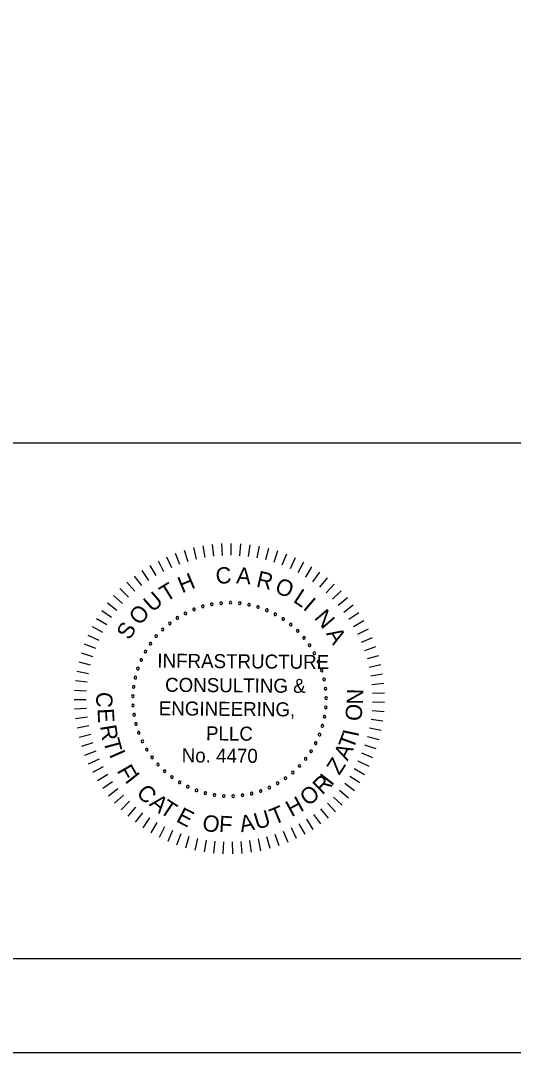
# Model space of a CAD drawing. Extents: x -125.5 to -89.4, y -5.1 to 16.9.
# Drawn here: x -100.31 to -97.69, y -5.07 to 0.43 of the extents above; entities that cross this region are included whole.
import ezdxf

# ---------------------------------------------------------------- set-up
doc = ezdxf.new("R2010")
doc.units = 0
for name, color, linetype in [('BR_BORDER LINES', 7, 'Continuous'), ('BR_TEXT', 7, 'Continuous'), ('Level 31', 7, 'Continuous')]:
    doc.layers.add(name, color=color, linetype=linetype)

msp = doc.modelspace()

# ---------------------------------------------------------------- linework, layer by layer
at = {"layer": 'BR_BORDER LINES'}
for p, q in [((-102.8989, -1.8161), (-97.5337, -1.8161)), ((-123.6994, -4.5662), (-90.0334, -4.5662))]:
    msp.add_line(p, q, dxfattribs=at)
at = {"layer": 'BR_TEXT'}
for p, q in [((-99.2931, -2.3579), (-99.2858, -2.4212)), ((-99.2427, -2.3538), (-99.2394, -2.4174)), ((-99.1923, -2.3527), (-99.1928, -2.4164)), ((-99.1418, -2.3548), (-99.1462, -2.4183)), ((-99.0916, -2.3599), (-99.0999, -2.423)), ((-99.489, -2.4048), (-99.4667, -2.4644)), ((-99.4412, -2.3886), (-99.4226, -2.4495)), ((-99.3925, -2.3754), (-99.3776, -2.4373)), ((-99.343, -2.3651), (-99.332, -2.4278)), ((-99.0418, -2.368), (-99.0539, -2.4305)), ((-98.9925, -2.3792), (-99.0084, -2.4408)), ((-98.9441, -2.3933), (-98.9637, -2.4539)), ((-98.8966, -2.4104), (-98.9199, -2.4696)), ((-99.6253, -2.4703), (-99.5926, -2.5249)), ((-99.5813, -2.4457), (-99.5519, -2.5022)), ((-99.5358, -2.4238), (-99.5099, -2.482)), ((-98.8502, -2.4303), (-98.877, -2.488)), ((-98.8051, -2.453), (-98.8354, -2.509)), ((-99.7086, -2.5273), (-99.6694, -2.5775)), ((-99.6678, -2.4975), (-99.6318, -2.55)), ((-98.7615, -2.4785), (-98.7952, -2.5325)), ((-98.7195, -2.5065), (-98.7564, -2.5584)), ((-99.7475, -2.5595), (-99.7053, -2.6072)), ((-98.6793, -2.5371), (-98.7193, -2.5866)), ((-98.6411, -2.57), (-98.684, -2.617)), ((-99.819, -2.6308), (-99.7713, -2.673)), ((-99.7843, -2.5941), (-99.7393, -2.6391)), ((-98.6049, -2.6052), (-98.6506, -2.6495)), ((-99.8513, -2.6695), (-99.8012, -2.7087)), ((-98.571, -2.6426), (-98.6193, -2.684)), ((-98.5393, -2.6819), (-98.5901, -2.7204)), ((-99.8813, -2.7102), (-99.8288, -2.7463)), ((-98.5102, -2.7232), (-98.5632, -2.7584)), ((-99.9334, -2.7965), (-99.877, -2.826)), ((-99.9087, -2.7526), (-99.8541, -2.7854)), ((-98.4836, -2.7661), (-98.5387, -2.798)), ((-99.9555, -2.842), (-99.8973, -2.8679)), ((-98.4597, -2.8105), (-98.5166, -2.839)), ((-98.4385, -2.8563), (-98.497, -2.8813)), ((-99.9747, -2.8886), (-99.9151, -2.911)), ((-98.4202, -2.9034), (-98.4801, -2.9248)), ((-99.991, -2.9364), (-99.9302, -2.9551)), ((-98.4047, -2.9514), (-98.4659, -2.9691)), ((-100.0044, -2.9851), (-99.9426, -3)), ((-98.3922, -3.0004), (-98.4544, -3.0143)), ((-100.0149, -3.0345), (-99.9522, -3.0456)), ((-98.3828, -3.05), (-98.4456, -3.0601)), ((-100.0266, -3.1347), (-99.963, -3.1382)), ((-100.0222, -3.0844), (-99.959, -3.0917)), ((-98.3763, -3.1), (-98.4397, -3.1063)), ((-100.0278, -3.1852), (-99.9641, -3.1847)), ((-98.373, -3.1504), (-98.4366, -3.1528)), ((-100.026, -3.2356), (-99.9625, -3.2313)), ((-98.3727, -3.2009), (-98.4363, -3.1994)), ((-100.0211, -3.2859), (-99.9579, -3.2777)), ((-98.3813, -3.3014), (-98.4443, -3.2922)), ((-98.3755, -3.2513), (-98.4389, -3.2459)), ((-100.0131, -3.3357), (-99.9506, -3.3237)), ((-98.3902, -3.3511), (-98.4525, -3.3381)), ((-100.0021, -3.385), (-99.9405, -3.3692)), ((-98.4021, -3.4002), (-98.4635, -3.3834)), ((-99.9882, -3.4335), (-99.9276, -3.414)), ((-99.9713, -3.4811), (-99.912, -3.4579)), ((-98.417, -3.4484), (-98.4773, -3.4279)), ((-99.9515, -3.5276), (-99.8937, -3.5008)), ((-98.4554, -3.5417), (-98.5128, -3.514)), ((-98.4348, -3.4957), (-98.4937, -3.4715)), ((-99.929, -3.5727), (-99.8729, -3.5425)), ((-98.4789, -3.5865), (-98.5344, -3.5553)), ((-99.9037, -3.6164), (-99.8496, -3.5828)), ((-99.8758, -3.6585), (-99.8239, -3.6217)), ((-98.505, -3.6297), (-98.5585, -3.5952)), ((-99.8454, -3.6988), (-99.7958, -3.6589)), ((-98.5648, -3.7109), (-98.6137, -3.6702)), ((-98.5336, -3.6712), (-98.5849, -3.6335)), ((-99.8126, -3.7372), (-99.7655, -3.6943)), ((-99.7775, -3.7735), (-99.7331, -3.7278)), ((-98.6341, -3.7843), (-98.6777, -3.7379)), ((-98.5983, -3.7487), (-98.6447, -3.705)), ((-99.7403, -3.8076), (-99.6988, -3.7593)), ((-99.701, -3.8393), (-99.6626, -3.7886)), ((-98.672, -3.8177), (-98.7126, -3.7687)), ((-99.6599, -3.8687), (-99.6246, -3.8157)), ((-99.6171, -3.8954), (-99.5851, -3.8404)), ((-98.7967, -3.9032), (-98.8278, -3.8476)), ((-98.7534, -3.8772), (-98.7879, -3.8237)), ((-98.7118, -3.8487), (-98.7494, -3.7974)), ((-99.5728, -3.9195), (-99.5442, -3.8626)), ((-99.527, -3.9408), (-99.5019, -3.8823)), ((-99.48, -3.9594), (-99.4586, -3.8994)), ((-98.935, -3.9645), (-98.9555, -3.9042)), ((-98.8877, -3.9469), (-98.9118, -3.888)), ((-98.8416, -3.9264), (-98.8692, -3.8691)), ((-99.432, -3.975), (-99.4143, -3.9138)), ((-99.3832, -3.9876), (-99.3692, -3.9255)), ((-99.3336, -3.9973), (-99.3234, -3.9344)), ((-99.2836, -4.0039), (-99.2772, -3.9406)), ((-99.2332, -4.0075), (-99.2307, -3.9438)), ((-99.1827, -4.0079), (-99.1841, -3.9443)), ((-99.1323, -4.0053), (-99.1376, -3.9419)), ((-99.0821, -3.9997), (-99.0913, -3.9367)), ((-99.0324, -3.991), (-99.0454, -3.9286)), ((-98.9833, -3.9792), (-99.0001, -3.9178))]:
    msp.add_line(p, q, dxfattribs=at)
for centre, start, end in [((-99.3424, -2.6889), 16.1422, 196.1422), ((-99.3424, -2.6889), 196.1422, 16.1422), ((-99.2939, -2.6775), 10.6038, 190.6038), ((-99.2939, -2.6775), 190.6038, 10.6038), ((-99.2445, -2.6708), 5.0653, 185.0653), ((-99.2445, -2.6708), 185.0653, 5.0653), ((-99.1947, -2.6689), 359.5268, 179.5268), ((-99.1947, -2.6689), 179.5268, 359.5268), ((-99.145, -2.6718), 173.9884, 353.9884), ((-99.145, -2.6718), 353.9884, 173.9884), ((-99.0957, -2.6795), 168.4499, 348.4499), ((-99.0957, -2.6795), 348.4499, 168.4499), ((-99.0475, -2.6919), 162.9114, 342.9114), ((-99.0475, -2.6919), 342.9114, 162.9114), ((-99.4782, -2.7503), 32.7576, 212.7576), ((-99.4782, -2.7503), 212.7576, 32.7576), ((-99.435, -2.7255), 27.2191, 207.2191), ((-99.435, -2.7255), 207.2191, 27.2191), ((-99.3896, -2.705), 21.6807, 201.6807), ((-99.3896, -2.705), 201.6807, 21.6807), ((-99.0006, -2.709), 157.373, 337.373), ((-99.0006, -2.709), 337.373, 157.373), ((-98.9557, -2.7304), 151.8345, 331.8345), ((-98.9557, -2.7304), 331.8345, 151.8345), ((-98.913, -2.7561), 326.2961, 146.2961), ((-99.5564, -2.8119), 43.8345, 223.8345), ((-99.5188, -2.7792), 38.2961, 218.2961), ((-99.5188, -2.7792), 218.2961, 38.2961), ((-98.913, -2.7561), 146.2961, 326.2961), ((-98.873, -2.7858), 140.7576, 320.7576), ((-98.873, -2.7858), 320.7576, 140.7576), ((-99.5907, -2.848), 49.373, 229.373), ((-99.5907, -2.848), 229.373, 49.373), ((-99.5564, -2.8119), 223.8345, 43.8345), ((-98.836, -2.8192), 135.2191, 315.2191), ((-98.836, -2.8192), 315.2191, 135.2191), ((-98.8024, -2.8561), 129.6807, 309.6807), ((-98.8024, -2.8561), 309.6807, 129.6807), ((-99.6214, -2.8873), 54.9114, 234.9114), ((-99.6214, -2.8873), 234.9114, 54.9114), ((-98.7726, -2.896), 124.1422, 304.1422), ((-98.7726, -2.896), 304.1422, 124.1422), ((-99.6706, -2.9738), 65.9884, 245.9884), ((-99.6706, -2.9738), 245.9884, 65.9884), ((-99.6481, -2.9293), 60.4499, 240.4499), ((-99.6481, -2.9293), 240.4499, 60.4499), ((-98.7467, -2.9386), 118.6038, 298.6038), ((-98.7467, -2.9386), 298.6038, 118.6038), ((-99.6888, -3.0202), 71.5268, 251.5268), ((-99.6888, -3.0202), 251.5268, 71.5268), ((-98.7251, -2.9835), 113.0653, 293.0653), ((-98.7251, -2.9835), 293.0653, 113.0653), ((-98.7079, -3.0302), 107.5268, 287.5268), ((-98.7079, -3.0302), 287.5268, 107.5268), ((-99.7024, -3.0681), 77.0653, 257.0653), ((-99.7024, -3.0681), 257.0653, 77.0653), ((-98.6953, -3.0785), 101.9884, 281.9884), ((-98.6953, -3.0785), 281.9884, 101.9884), ((-99.7113, -3.1172), 82.6038, 262.6038), ((-99.7113, -3.1172), 262.6038, 82.6038), ((-98.6874, -3.1277), 96.4499, 276.4499), ((-98.6874, -3.1277), 276.4499, 96.4499), ((-99.7154, -3.1668), 88.1422, 268.1422), ((-99.7154, -3.1668), 268.1422, 88.1422), ((-98.6843, -3.1774), 90.9114, 270.9114), ((-98.6843, -3.1774), 270.9114, 90.9114), ((-99.7147, -3.2167), 93.6807, 273.6807), ((-99.7147, -3.2167), 273.6807, 93.6807), ((-98.686, -3.2272), 85.373, 265.373), ((-98.686, -3.2272), 265.373, 85.373), ((-99.7092, -3.2662), 99.2191, 279.2191), ((-99.7092, -3.2662), 279.2191, 99.2191), ((-98.6926, -3.2766), 79.8345, 259.8345), ((-98.6926, -3.2766), 259.8345, 79.8345), ((-99.6989, -3.3149), 104.7576, 284.7576), ((-99.6989, -3.3149), 284.7576, 104.7576), ((-98.7038, -3.3251), 74.2961, 254.2961), ((-98.7038, -3.3251), 254.2961, 74.2961), ((-99.684, -3.3625), 110.2961, 290.2961), ((-99.684, -3.3625), 290.2961, 110.2961), ((-99.6646, -3.4084), 115.8345, 295.8345), ((-99.6646, -3.4084), 295.8345, 115.8345), ((-98.7197, -3.3724), 68.7576, 248.7576), ((-98.7197, -3.3724), 248.7576, 68.7576), ((-99.6408, -3.4522), 121.373, 301.373), ((-99.6408, -3.4522), 301.373, 121.373), ((-98.7647, -3.4611), 57.6807, 237.6807), ((-98.7647, -3.4611), 237.6807, 57.6807), ((-98.7401, -3.4178), 63.2191, 243.2191), ((-98.7401, -3.4178), 243.2191, 63.2191), ((-99.6129, -3.4935), 126.9114, 306.9114), ((-99.6129, -3.4935), 306.9114, 126.9114), ((-98.7934, -3.5019), 52.1422, 232.1422), ((-98.7934, -3.5019), 232.1422, 52.1422), ((-99.5812, -3.5319), 132.4499, 312.4499), ((-99.5812, -3.5319), 312.4499, 132.4499), ((-99.5459, -3.5671), 137.9884, 317.9884), ((-99.5459, -3.5671), 317.9884, 137.9884), ((-98.862, -3.5741), 41.0653, 221.0653), ((-98.862, -3.5741), 221.0653, 41.0653), ((-98.826, -3.5396), 46.6038, 226.6038), ((-98.826, -3.5396), 226.6038, 46.6038), ((-99.5074, -3.5987), 143.5268, 323.5268), ((-99.5074, -3.5987), 323.5268, 143.5268), ((-99.466, -3.6264), 149.0653, 329.0653), ((-99.466, -3.6264), 329.0653, 149.0653), ((-98.9431, -3.6317), 29.9884, 209.9884), ((-98.9431, -3.6317), 209.9884, 29.9884), ((-98.9012, -3.6049), 35.5268, 215.5268), ((-98.9012, -3.6049), 215.5268, 35.5268), ((-99.4221, -3.65), 154.6038, 334.6038), ((-99.4221, -3.65), 334.6038, 154.6038), ((-99.3761, -3.6693), 160.1422, 340.1422), ((-99.3761, -3.6693), 340.1422, 160.1422), ((-99.3285, -3.684), 165.6807, 345.6807), ((-99.3285, -3.684), 345.6807, 165.6807), ((-99.0817, -3.6865), 13.373, 193.373), ((-99.0817, -3.6865), 193.373, 13.373), ((-99.0338, -3.6728), 18.9114, 198.9114), ((-99.0338, -3.6728), 198.9114, 18.9114), ((-98.9875, -3.6545), 24.4499, 204.4499), ((-98.9875, -3.6545), 204.4499, 24.4499), ((-99.2797, -3.6941), 351.2191, 171.2191), ((-99.2797, -3.6941), 171.2191, 351.2191), ((-99.2302, -3.6994), 356.7576, 176.7576), ((-99.2302, -3.6994), 176.7576, 356.7576), ((-99.1803, -3.6999), 2.2961, 182.2961), ((-99.1803, -3.6999), 182.2961, 2.2961), ((-99.1307, -3.6956), 7.8345, 187.8345), ((-99.1307, -3.6956), 187.8345, 7.8345)]:
    msp.add_arc(centre, 0.00701, start, end, dxfattribs=at)
at = {"layer": 'Level 31'}
msp.add_lwpolyline([(-125.5328, -5.0661), (-89.5328, -5.0661), (-89.5328, 16.9339), (-125.5328, 16.9339)], close=True, dxfattribs=at)

# ---------------------------------------------------------------- texts
at = {"layer": 'BR_TEXT'}
for s, height, rotation, p in [('H', 0.0872, 22.7882, (-99.453, -2.6197)), ('C', 0.0872, 4.7281, (-99.2702, -2.5703)), ('A', 0.0872, 355.6981, (-99.1657, -2.5654)), ('R', 0.0872, 346.6681, (-99.0615, -2.5824)), ('T', 0.0872, 31.8182, (-99.5379, -2.6674)), ('O', 0.0872, 337.638, (-98.9637, -2.6122)), ('U', 0.0872, 40.8482, (-99.6112, -2.7235)), ('L', 0.0872, 327.108, (-98.8649, -2.6626)), ('O', 0.0872, 49.8782, (-99.6782, -2.7945)), ('I', 0.0872, 319.578, (-98.8123, -2.7005)), ('N', 0.0872, 310.548, (-98.7515, -2.7512)), ('S', 0.0872, 58.9083, (-99.7336, -2.8727)), ('A', 0.0872, 301.5179, (-98.6864, -2.8336)), ('INFRASTRUCTURE', 0.074771, 359.5268, (-99.585, -3.0152)), ('CONSULTING &', 0.074771, 359.5268, (-99.5437, -3.1438)), ('C', 0.0872, 267.025, (-99.9086, -3.1426)), ('N', 0.0872, 89.2085, (-98.4872, -3.2124)), ('E', 0.0872, 273.025, (-99.9042, -3.2342)), ('ENGINEERING,', 0.074771, 359.5268, (-99.5773, -3.2693)), ('O', 0.0872, 83.2085, (-98.4982, -3.3038)), ('R', 0.0872, 279.025, (-99.8914, -3.3265)), ('PLLC', 0.07477, 359.5268, (-99.3256, -3.4028)), ('I', 0.0872, 77.9093, (-98.5137, -3.3881)), ('T', 0.0872, 285.025, (-99.874, -3.4053)), ('T', 0.0872, 69.3954, (-98.5394, -3.4556)), ('I', 0.0872, 293.7713, (-99.8443, -3.4784)), ('No. 4470', 0.07477, 359.5268, (-99.4551, -3.5197)), ('A', 0.0872, 63.3954, (-98.5702, -3.516)), ('Z', 0.0872, 57.3954, (-98.6141, -3.5923)), ('F', 0.0872, 299.7713, (-99.8031, -3.5644)), ('I', 0.0872, 308.5268, (-99.761, -3.6183)), ('R', 0.0872, 44.5268, (-98.7045, -3.6973)), ('I', 0.0872, 52.3339, (-98.6551, -3.65)), ('C', 0.0872, 314.5268, (-99.7017, -3.6884)), ('O', 0.0872, 38.5268, (-98.7811, -3.7572)), ('A', 0.0872, 320.5268, (-99.6325, -3.747)), ('T', 0.0872, 326.5268, (-99.5781, -3.7855)), ('H', 0.0872, 28.5268, (-98.8692, -3.8132)), ('E', 0.0872, 332.5268, (-99.4895, -3.8332)), ('U', 0.0872, 16.5268, (-99.0541, -3.8794)), ('T', 0.0872, 22.5268, (-98.9624, -3.855)), ('O', 0.0872, 350.5268, (-99.3494, -3.8821)), ('F', 0.0872, 356.5268, (-99.2579, -3.8912)), ('A', 0.0872, 10.5268, (-99.138, -3.8929))]:
    msp.add_text(s, height=height, rotation=rotation, dxfattribs=at).set_placement(p)

doc.saveas('drawing.dxf')
